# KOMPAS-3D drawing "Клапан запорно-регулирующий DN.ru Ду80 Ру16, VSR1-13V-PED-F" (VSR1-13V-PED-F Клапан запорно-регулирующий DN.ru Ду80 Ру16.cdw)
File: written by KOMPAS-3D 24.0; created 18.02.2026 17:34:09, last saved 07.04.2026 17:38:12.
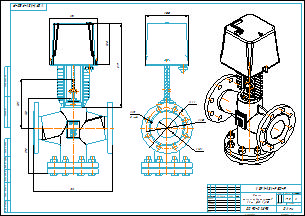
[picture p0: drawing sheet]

Document properties: Автор: R2D2; Форматы листов документа: A2; Полное имя файла: VSR1-13V-PED-F Клапан запорно-регулирующий DN.ru Ду80 Ру16.m3d; Масса: 27.5; Наименование: Клапан запорно-регулирующий DN.ru Ду80 Ру16; Количество листов документа: 1; Примечание: D090-02893

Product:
- Part/product: Клапан запорно-регулирующий DN.ru Ду80 Ру16  | designation VSR1-13V-PED-F
    Масса: 27.5
    Раздел спецификации: Прочие изделия
    Примечание: D090-02893

Views: Вид 1, Спереди
Referenced files in E:\Работа\Зайцев\Солянка\VSR1-13V-PED-F Клапан запорно-регулирующий DN.ru\DN15\DN15 Kv0.16\: VSR1-13V-PED-F Клапан запорно-регулирующий DN.ru Ду15 Ру16.m3d
Referenced files in E:\Работа\Зайцев\Солянка\VSR1-13V-PED-F Клапан запорно-регулирующий DN.ru\DN80\: VSR1-13V-PED-F Клапан запорно-регулирующий DN.ru Ду80 Ру16.m3d
Referenced files in E:\Работа\Зайцев\Для компаса\: чертеж DN.ru А3.cdt
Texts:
  Линейный размер
  VSR1-13V-PED-F
  чертеж DN.ru А3.cdt
  Клапан
  запорно-регулирующий
  DN.ru Ду80 Ру16
  Клапан запорно-регулирующий DN.ru Ду80 Ру16
  VSR1-13V-PED-F Клапан запорно-регулирующий DN.ru Ду80 Ру16
Dimensions and other numbers on the sheet: 0; 3; 2; 4; 310; 175; 116; 191; 190; 327; 158; 1:2; 1; 27,5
